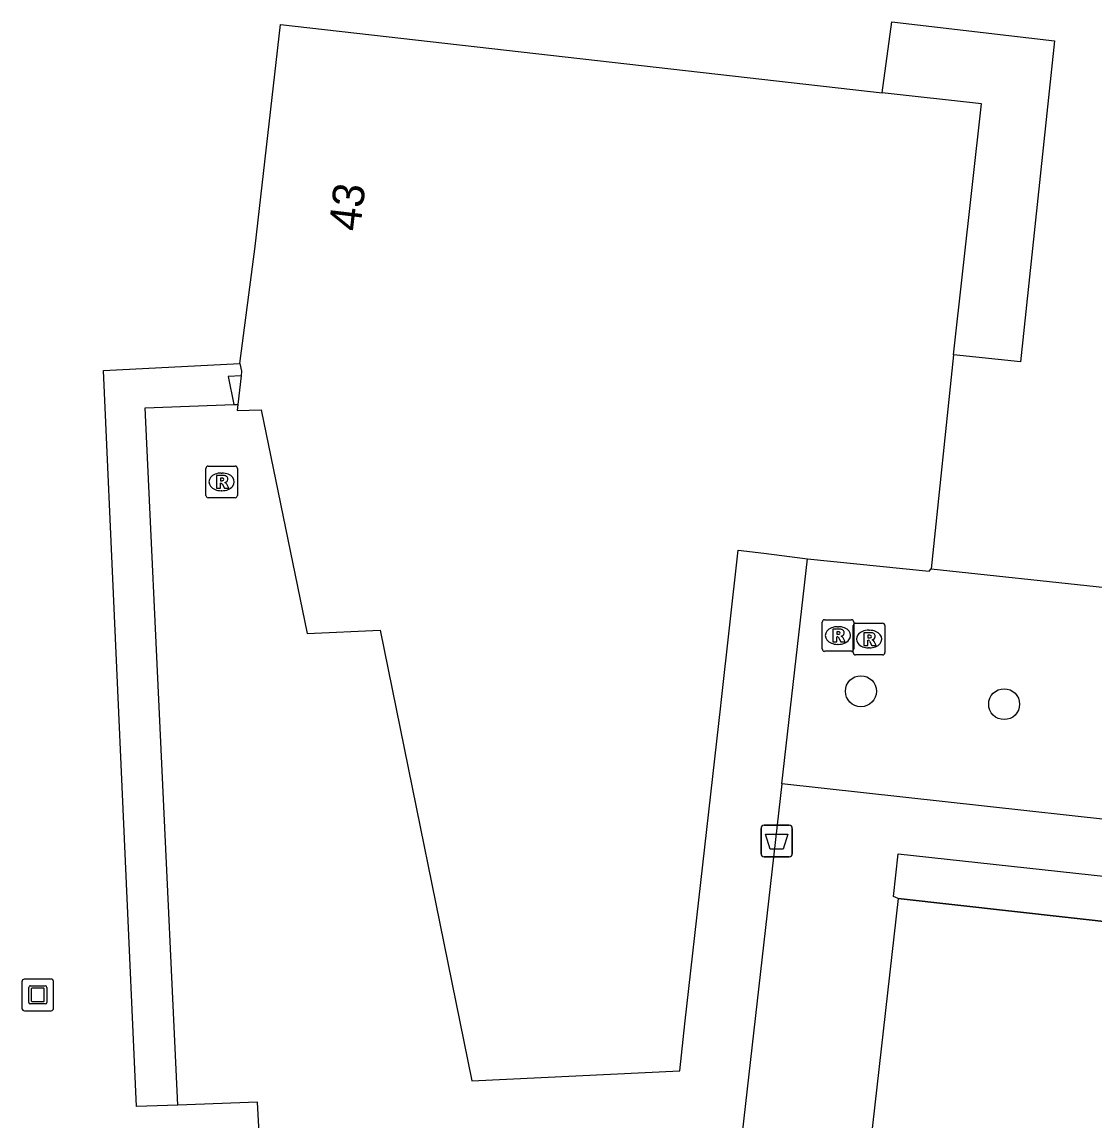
# Model space of a CAD drawing. Extents: x 162515 to 163909, y 388494 to 389773.
# Drawn here: x 162712.89 to 162746.82, y 388666.71 to 388701.45 of the extents above; entities that cross this region are included whole.
import ezdxf

# ---------------------------------------------------------------- set-up
doc = ezdxf.new("R2010")
doc.units = 0
for name, color, linetype in [('IMGEO_Afvalbak', 7, 'Continuous'), ('IMGEO_Boom', 7, 'Continuous'), ('IMGEO_Haag', 7, 'Continuous'), ('IMGEO_Hek', 7, 'Continuous'), ('IMGEO_Kunstobject', 7, 'Continuous'), ('IMGEO_Pand', 7, 'Continuous'), ('IMGEO_Pand_nummerreeks', 7, 'Continuous'), ('IMGEO_Rioolput', 7, 'Continuous'), ('IMGEO_Voetpad_open', 7, 'Continuous')]:
    doc.layers.add(name, color=color, linetype=linetype)

msp = doc.modelspace()

# ---------------------------------------------------------------- linework, layer by layer
at = {"layer": 'IMGEO_Afvalbak'}
for p, q in [((162736.377, 388676.039), (162737.167, 388676.039)), ((162737.167, 388676.039), (162736.377, 388676.039)), ((162736.277, 388675.139), (162736.277, 388675.939)), ((162736.277, 388675.939), (162736.277, 388675.139)), ((162737.267, 388675.939), (162737.267, 388675.139)), ((162737.267, 388675.139), (162737.267, 388675.939)), ((162737.167, 388675.039), (162736.377, 388675.039)), ((162736.377, 388675.039), (162737.167, 388675.039))]:
    msp.add_line(p, q, dxfattribs=at)
msp.add_lwpolyline([(162736.42, 388675.753), (162737.124, 388675.753), (162736.975, 388675.283), (162736.569, 388675.283), (162736.42, 388675.753)], dxfattribs=at)
for centre, start, end in [((162736.377, 388675.939), 90, 180), ((162736.377, 388675.939), 90, 180), ((162737.167, 388675.939), 0, 90), ((162737.167, 388675.939), 360, 90), ((162736.377, 388675.139), 180, 270), ((162736.377, 388675.139), 180, 270), ((162737.167, 388675.139), 270, 0), ((162737.167, 388675.139), 270, 0)]:
    msp.add_arc(centre, 0.1, start, end, dxfattribs=at)
at = {"layer": 'IMGEO_Boom'}
for centre in [(162739.438, 388680.279), (162743.971, 388679.869)]:
    msp.add_circle(centre, 0.489, dxfattribs=at)
at = {"layer": 'IMGEO_Haag'}
msp.add_lwpolyline([(162774.694, 388669.917), (162740.619, 388673.72)], dxfattribs=at)
at = {"layer": 'IMGEO_Hek'}
msp.add_lwpolyline([(162740.619, 388673.72), (162774.694, 388669.917)], dxfattribs=at)
at = {"layer": 'IMGEO_Kunstobject'}
for p, q in [((162713.803, 388671.173), (162712.962, 388671.173)), ((162713.803, 388671.173), (162712.962, 388671.173)), ((162712.887, 388671.089), (162712.887, 388670.248)), ((162712.887, 388671.089), (162712.887, 388670.248)), ((162713.101, 388670.437), (162713.101, 388670.911)), ((162713.151, 388670.961), (162713.625, 388670.961)), ((162713.181, 388670.861), (162713.181, 388670.487)), ((162713.575, 388670.881), (162713.201, 388670.881)), ((162713.595, 388670.487), (162713.595, 388670.861)), ((162713.675, 388670.911), (162713.675, 388670.437)), ((162713.887, 388670.257), (162713.887, 388671.098)), ((162713.887, 388670.257), (162713.887, 388671.098)), ((162713.201, 388670.467), (162713.575, 388670.467)), ((162712.971, 388670.173), (162713.812, 388670.173)), ((162712.971, 388670.173), (162713.812, 388670.173)), ((162713.625, 388670.387), (162713.151, 388670.387))]:
    msp.add_line(p, q, dxfattribs=at)
for centre, radius, start, end in [((162712.965, 388671.095), 0.0779, 92.4484, 184.2845), ((162712.965, 388671.095), 0.0779, 92.4484, 184.2845), ((162713.809, 388671.095), 0.0779, 2.4484, 94.2845), ((162713.809, 388671.095), 0.0779, 2.4484, 94.2845), ((162713.151, 388670.911), 0.05, 90, 180), ((162713.201, 388670.861), 0.02, 90, 180), ((162713.575, 388670.861), 0.02, 360, 90), ((162713.625, 388670.911), 0.05, 360, 90), ((162713.151, 388670.437), 0.05, 180, 270), ((162713.201, 388670.487), 0.02, 180, 270), ((162713.575, 388670.487), 0.02, 270, 0), ((162713.625, 388670.437), 0.05, 270, 0), ((162712.965, 388670.251), 0.0779, 182.4484, 274.2845), ((162712.965, 388670.251), 0.0779, 182.4484, 274.2845), ((162713.809, 388670.251), 0.0779, 272.4484, 4.2845), ((162713.809, 388670.251), 0.0779, 272.4484, 4.2845)]:
    msp.add_arc(centre, radius, start, end, dxfattribs=at)
at = {"layer": 'IMGEO_Pand'}
for points in [[(162719.784, 388690.65), (162720.273, 388694.343), (162721.067, 388701.371), (162740.115, 388699.212)], [(162742.365, 388690.923), (162743.258, 388698.856), (162740.115, 388699.212)], [(162719.784, 388690.65), (162719.835, 388690.406), (162719.821, 388690.257)], [(162742.365, 388690.923), (162741.658, 388684.153)], [(162719.821, 388690.257), (162719.72, 388689.352)], [(162719.72, 388689.352), (162719.698, 388689.154), (162720.455, 388689.183), (162721.909, 388682.106), (162724.223, 388682.206), (162727.123, 388667.951), (162733.703, 388668.271), (162733.871, 388669.761), (162735.002, 388679.821), (162735.014, 388679.927), (162735.555, 388684.736), (162736.368, 388684.647), (162737.75, 388684.462)], [(162737.75, 388684.462), (162741.594, 388684.073), (162741.658, 388684.153)]]:
    msp.add_lwpolyline(points, dxfattribs=at)
at = {"layer": 'IMGEO_Rioolput'}
for p, q in [((162718.706, 388686.475), (162718.706, 388687.327)), ((162718.781, 388687.401), (162719.633, 388687.401)), ((162719.194, 388687.181), (162719.219, 388687.181)), ((162719.707, 388687.327), (162719.707, 388686.475)), ((162719.217, 388686.621), (162719.192, 388686.621)), ((162719.633, 388686.401), (162718.781, 388686.401)), ((162738.211, 388681.615), (162738.211, 388682.467)), ((162738.286, 388682.541), (162739.138, 388682.541)), ((162738.699, 388682.321), (162738.724, 388682.321)), ((162739.196, 388681.502), (162739.196, 388682.354)), ((162739.212, 388682.467), (162739.212, 388681.615)), ((162739.271, 388682.428), (162740.123, 388682.428)), ((162740.197, 388682.354), (162740.197, 388681.502)), ((162739.684, 388682.208), (162739.709, 388682.208)), ((162738.722, 388681.761), (162738.697, 388681.761)), ((162739.707, 388681.648), (162739.682, 388681.648)), ((162739.138, 388681.541), (162738.286, 388681.541)), ((162740.123, 388681.428), (162739.271, 388681.428))]:
    msp.add_line(p, q, dxfattribs=at)
for points in [[(162718.706, 388686.475), (162718.706, 388687.327)], [(162718.781, 388687.401), (162719.633, 388687.401)], [(162719.707, 388687.327), (162719.707, 388686.475)], [(162719.295, 388687.099), (162719.043, 388687.101), (162719.043, 388686.701)], [(162719.043, 388686.701), (162719.167, 388686.701), (162719.167, 388686.863), (162719.178, 388686.863)], [(162719.221, 388687.02), (162719.167, 388687.02), (162719.167, 388686.939)], [(162719.167, 388686.939), (162719.219, 388686.939)], [(162719.225, 388686.834), (162719.296, 388686.701), (162719.436, 388686.701), (162719.371, 388686.827)], [(162719.633, 388686.401), (162718.781, 388686.401)], [(162738.211, 388681.615), (162738.211, 388682.467)], [(162738.286, 388682.541), (162739.138, 388682.541)], [(162739.196, 388681.502), (162739.196, 388682.354)], [(162739.212, 388682.467), (162739.212, 388681.615)], [(162739.271, 388682.428), (162740.123, 388682.428)], [(162740.197, 388682.354), (162740.197, 388681.502)], [(162738.8, 388682.239), (162738.548, 388682.241), (162738.548, 388681.841)], [(162738.548, 388681.841), (162738.672, 388681.841), (162738.672, 388682.003), (162738.683, 388682.003)], [(162738.726, 388682.16), (162738.672, 388682.16), (162738.672, 388682.079)], [(162738.672, 388682.079), (162738.724, 388682.079)], [(162738.73, 388681.974), (162738.801, 388681.841), (162738.941, 388681.841), (162738.876, 388681.967)], [(162739.785, 388682.126), (162739.533, 388682.128), (162739.533, 388681.728)], [(162739.711, 388682.047), (162739.657, 388682.047), (162739.657, 388681.966)], [(162739.657, 388681.966), (162739.709, 388681.966)], [(162739.533, 388681.728), (162739.657, 388681.728), (162739.657, 388681.89), (162739.668, 388681.89)], [(162739.715, 388681.861), (162739.786, 388681.728), (162739.926, 388681.728), (162739.861, 388681.854)], [(162739.138, 388681.541), (162738.286, 388681.541)], [(162740.123, 388681.428), (162739.271, 388681.428)]]:
    msp.add_lwpolyline(points, dxfattribs=at)
for centre, radius, start, end in [((162718.783, 388687.325), 0.0765, 91.552, 178.448), ((162718.783, 388687.325), 0.0765, 91.552, 178.448), ((162719.631, 388687.325), 0.0765, 1.552, 88.448), ((162719.631, 388687.325), 0.0765, 1.552, 88.448), ((162719.177, 388686.81), 0.0533, 26.0293, 88.6989), ((162719.203, 388687.128), 0.19, 274.7715, 282.9687), ((162719.227, 388686.924), 0.0964, 77.0061, 93.1865), ((162719.241, 388686.981), 0.0378, 276.6634, 79.6772), ((162719.294, 388686.989), 0.109, 350.3612, 89.416), ((162719.292, 388686.989), 0.112, 277.5842, 350.9817), ((162719.276, 388686.774), 0.108, 29.5134, 73.7905), ((162718.783, 388686.477), 0.0765, 181.552, 268.448), ((162718.783, 388686.477), 0.0765, 181.552, 268.448), ((162719.631, 388686.477), 0.0765, 271.552, 358.448), ((162719.631, 388686.477), 0.0765, 271.552, 358.448), ((162738.288, 388682.465), 0.0765, 91.552, 178.448), ((162738.288, 388682.465), 0.0765, 91.552, 178.448), ((162739.136, 388682.465), 0.0765, 1.552, 88.448), ((162739.136, 388682.465), 0.0765, 1.552, 88.448), ((162739.273, 388682.352), 0.0765, 91.552, 178.448), ((162739.273, 388682.352), 0.0765, 91.552, 178.448), ((162740.121, 388682.352), 0.0765, 1.552, 88.448), ((162740.121, 388682.352), 0.0765, 1.552, 88.448), ((162738.682, 388681.95), 0.0533, 26.0293, 88.6989), ((162738.708, 388682.268), 0.19, 274.7715, 282.9687), ((162738.732, 388682.064), 0.0964, 77.0061, 93.1865), ((162738.746, 388682.121), 0.0378, 276.6634, 79.6772), ((162738.799, 388682.129), 0.109, 350.3612, 89.416), ((162738.797, 388682.129), 0.112, 277.5842, 350.9817), ((162738.781, 388681.914), 0.108, 29.5134, 73.7905), ((162739.693, 388682.155), 0.19, 274.7715, 282.9687), ((162739.717, 388681.951), 0.0964, 77.0061, 93.1865), ((162739.731, 388682.008), 0.0378, 276.6634, 79.6772), ((162739.784, 388682.016), 0.109, 350.3612, 89.416), ((162739.782, 388682.016), 0.112, 277.5842, 350.9817), ((162739.766, 388681.801), 0.108, 29.5134, 73.7905), ((162738.288, 388681.617), 0.0765, 181.552, 268.448), ((162738.288, 388681.617), 0.0765, 181.552, 268.448), ((162739.136, 388681.617), 0.0765, 271.552, 358.448), ((162739.136, 388681.617), 0.0765, 271.552, 358.448), ((162739.667, 388681.837), 0.0533, 26.0293, 88.6989), ((162739.273, 388681.504), 0.0765, 181.552, 268.448), ((162739.273, 388681.504), 0.0765, 181.552, 268.448), ((162740.121, 388681.504), 0.0765, 271.552, 358.448), ((162740.121, 388681.504), 0.0765, 271.552, 358.448)]:
    msp.add_arc(centre, radius, start, end, dxfattribs=at)
for centre, major_axis, ratio, start_param, end_param in [((162719.193, 388686.901), (-0.387, 0.002), 0.722429, 4.712389, 7.853982), ((162719.218, 388686.901), (-0.39, 0.002), 0.717154, 1.570796, 4.712389), ((162738.698, 388682.041), (-0.387, 0.002), 0.722429, 4.712389, 7.853982), ((162738.723, 388682.041), (-0.39, 0.002), 0.717154, 1.570796, 4.712389), ((162739.683, 388681.928), (-0.387, 0.002), 0.722429, 4.712389, 7.853982), ((162739.708, 388681.928), (-0.39, 0.002), 0.717154, 1.570796, 4.712389)]:
    msp.add_ellipse(centre, major_axis=major_axis, ratio=ratio, start_param=start_param, end_param=end_param, dxfattribs=at)
at = {"layer": 'IMGEO_Voetpad_open'}
for points in [[(162740.115, 388699.212), (162740.416, 388701.449), (162745.568, 388700.847), (162744.485, 388690.701), (162742.365, 388690.923)], [(162741.658, 388684.153), (162747.179, 388683.562), (162748.144, 388692.361)], [(162753.984, 388691.735), (162755.444, 388691.555), (162753.788, 388675.49), (162736.932, 388677.352)], [(162717.822, 388667.183), (162716.51, 388667.141), (162715.465, 388690.422), (162719.784, 388690.65)], [(162719.821, 388690.257), (162719.415, 388690.238), (162719.597, 388689.348)], [(162717.822, 388667.183), (162716.782, 388689.248), (162719.597, 388689.348)], [(162719.597, 388689.348), (162719.72, 388689.352)], [(162736.932, 388677.352), (162737.75, 388684.462)], [(162736.932, 388677.352), (162732.278, 388636.348)], [(162740.619, 388673.72), (162740.467, 388673.786), (162740.619, 388675.132), (162748.764, 388674.252), (162775.448, 388671.453)], [(162740.619, 388673.72), (162736.498, 388637.358)], [(162720.495, 388664.363), (162720.338, 388667.285), (162717.822, 388667.183)]]:
    msp.add_lwpolyline(points, dxfattribs=at)

# ---------------------------------------------------------------- texts
at = {"layer": 'IMGEO_Pand_nummerreeks'}
msp.add_text('43', height=1, rotation=83.1767, dxfattribs=at).set_placement((162723.584, 388694.803))

doc.saveas('drawing.dxf')
